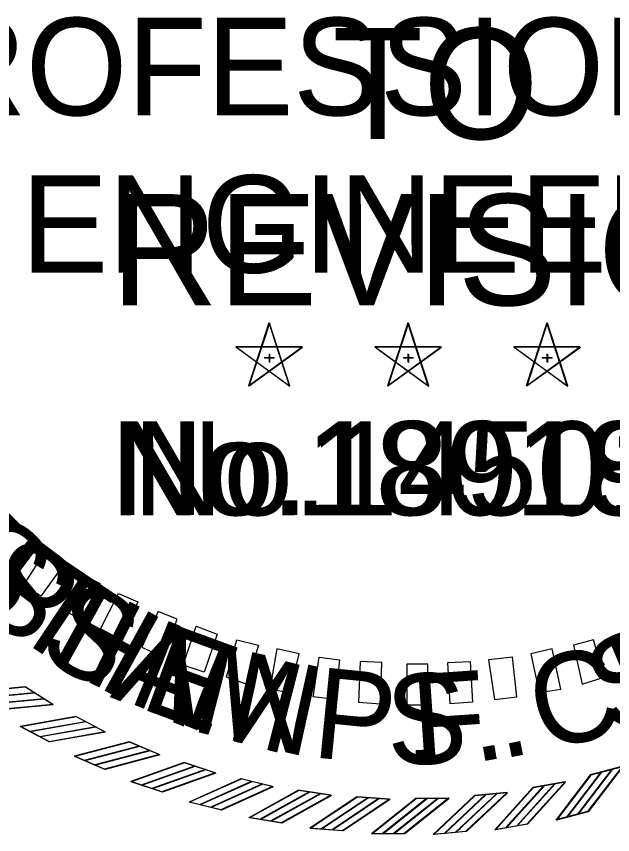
# Model space of a CAD drawing. Extents: x 16 to 1228740, y 11 to 152440.
# Drawn here: x 17.7202 to 17.7889, y 10.8149 to 10.9091 of the extents above; entities that cross this region are included whole.
import ezdxf

# ---------------------------------------------------------------- set-up
doc = ezdxf.new("R2010")
doc.units = 0
for name, color, linetype in [('STAMP_FRED', 7, 'Continuous'), ('STAMP_HUSSAM', 7, 'Continuous'), ('STAMP_JUSTIN', 7, 'Continuous'), ('STAMP_PRELIM', 7, 'Continuous')]:
    doc.layers.add(name, color=color, linetype=linetype)

msp = doc.modelspace()

# ---------------------------------------------------------------- linework, layer by layer
at = {"layer": 'STAMP_FRED'}
for p, q in [((17.749354, 10.873788), (17.746995, 10.866552)), ((17.751704, 10.866556), (17.749359, 10.873797)), ((17.765345, 10.873788), (17.762986, 10.866552)), ((17.767695, 10.866556), (17.76535, 10.873797)), ((17.781336, 10.873788), (17.778977, 10.866552)), ((17.783686, 10.866556), (17.781341, 10.873797)), ((17.753156, 10.871026), (17.745545, 10.871033)), ((17.745552, 10.871026), (17.751705, 10.866547)), ((17.747004, 10.866556), (17.753165, 10.871024)), ((17.769147, 10.871026), (17.761536, 10.871033)), ((17.761543, 10.871026), (17.767696, 10.866547)), ((17.762995, 10.866556), (17.769157, 10.871024)), ((17.785138, 10.871026), (17.777527, 10.871033)), ((17.777534, 10.871026), (17.783687, 10.866547)), ((17.778986, 10.866556), (17.785148, 10.871024)), ((17.748812, 10.86981), (17.749943, 10.86981)), ((17.749361, 10.870216), (17.749361, 10.869262)), ((17.764803, 10.86981), (17.765934, 10.86981)), ((17.765352, 10.870216), (17.765352, 10.869262)), ((17.780794, 10.86981), (17.781926, 10.86981)), ((17.781343, 10.870216), (17.781343, 10.869262)), ((17.724453, 10.82985), (17.721271, 10.831887)), ((17.730467, 10.826715), (17.727127, 10.828483)), ((17.724043, 10.825577), (17.720711, 10.82734)), ((17.736719, 10.824088), (17.733245, 10.825574)), ((17.730412, 10.822423), (17.726946, 10.823905)), ((17.743167, 10.821986), (17.739582, 10.82318)), ((17.789989, 10.822716), (17.786335, 10.821755)), ((17.737019, 10.819806), (17.733442, 10.820997)), ((17.749767, 10.820424), (17.746096, 10.821318)), ((17.783441, 10.820949), (17.77972, 10.820293)), ((17.756473, 10.819412), (17.75274, 10.82)), ((17.77677, 10.819729), (17.773007, 10.819382)), ((17.743819, 10.817743), (17.740156, 10.818635)), ((17.76324, 10.818958), (17.759471, 10.819235)), ((17.770021, 10.819064), (17.766242, 10.819029)), ((17.750767, 10.81625), (17.747043, 10.816836)), ((17.786034, 10.817528), (17.782388, 10.816569)), ((17.779072, 10.816105), (17.775359, 10.81545)), ((17.757815, 10.815335), (17.754055, 10.815611)), ((17.764913, 10.815005), (17.761144, 10.81497)), ((17.772015, 10.815262), (17.768261, 10.814916))]:
    msp.add_line(p, q, dxfattribs=at)
for points in [[(17.721273, 10.831883), (17.714778, 10.831278)], [(17.722324, 10.831196), (17.715829, 10.830591)], [(17.723443, 10.830514), (17.716948, 10.829909)], [(17.724459, 10.82985), (17.717964, 10.829245)], [(17.72713, 10.828479), (17.720707, 10.827339)], [(17.728235, 10.827881), (17.721812, 10.826742)], [(17.729406, 10.827294), (17.722983, 10.826155)], [(17.730473, 10.826716), (17.72405, 10.825577)], [(17.733248, 10.82557), (17.726941, 10.823904)], [(17.734398, 10.825065), (17.728091, 10.8234)], [(17.735614, 10.824577), (17.729307, 10.822911)], [(17.736725, 10.82409), (17.730418, 10.822424)], [(17.739586, 10.823176), (17.733438, 10.820996)], [(17.740774, 10.822769), (17.734626, 10.820588)], [(17.742025, 10.822382), (17.735877, 10.820201)], [(17.788816, 10.822423), (17.784862, 10.817235)], [(17.789992, 10.822721), (17.786038, 10.817533)], [(17.743173, 10.821988), (17.737025, 10.819807)], [(17.78634, 10.821754), (17.782386, 10.816565)], [(17.787557, 10.822062), (17.783603, 10.816874)], [(17.746099, 10.821314), (17.740152, 10.818633)], [(17.747317, 10.821006), (17.74137, 10.818325)], [(17.748596, 10.820724), (17.742649, 10.818043)], [(17.780964, 10.820498), (17.776595, 10.815654)], [(17.782248, 10.820754), (17.777879, 10.81591)], [(17.783445, 10.820954), (17.779076, 10.81611)], [(17.749772, 10.820427), (17.743826, 10.817746)], [(17.752744, 10.819997), (17.747039, 10.816834)], [(17.753983, 10.81979), (17.748278, 10.816627)], [(17.755281, 10.819615), (17.749576, 10.816452)], [(17.775565, 10.819633), (17.770811, 10.815166)], [(17.776774, 10.819733), (17.77202, 10.815266)], [(17.779725, 10.820291), (17.775356, 10.815447)], [(17.756478, 10.819415), (17.750773, 10.816252)], [(17.759475, 10.819232), (17.754051, 10.815609)], [(17.760727, 10.819128), (17.755303, 10.815505)], [(17.762035, 10.819061), (17.756611, 10.815438)], [(17.763245, 10.818961), (17.75782, 10.815338)], [(17.766247, 10.819026), (17.76114, 10.814967)], [(17.767503, 10.819026), (17.762396, 10.814967)], [(17.768812, 10.819067), (17.763705, 10.815008)], [(17.770025, 10.819067), (17.764919, 10.815008)], [(17.773012, 10.81938), (17.768258, 10.814913)], [(17.774264, 10.819484), (17.76951, 10.815017)]]:
    msp.add_lwpolyline(points, dxfattribs=at)
at = {"layer": 'STAMP_HUSSAM'}
for p, q in [((17.749298, 10.873819), (17.746939, 10.866583)), ((17.751648, 10.866587), (17.749303, 10.873827)), ((17.765289, 10.873819), (17.76293, 10.866583)), ((17.767639, 10.866587), (17.765294, 10.873827)), ((17.78128, 10.873819), (17.778922, 10.866583)), ((17.78363, 10.866587), (17.781285, 10.873827)), ((17.7531, 10.871057), (17.745489, 10.871064)), ((17.745496, 10.871057), (17.751649, 10.866577)), ((17.746948, 10.866587), (17.75311, 10.871055)), ((17.769091, 10.871057), (17.761481, 10.871064)), ((17.761487, 10.871057), (17.76764, 10.866577)), ((17.762939, 10.866587), (17.769101, 10.871055)), ((17.785082, 10.871057), (17.777472, 10.871064)), ((17.777478, 10.871057), (17.783631, 10.866577)), ((17.77893, 10.866587), (17.785092, 10.871055)), ((17.748756, 10.869841), (17.749887, 10.869841)), ((17.749305, 10.870247), (17.749305, 10.869292)), ((17.764747, 10.869841), (17.765879, 10.869841)), ((17.765296, 10.870247), (17.765296, 10.869292)), ((17.780738, 10.869841), (17.78187, 10.869841)), ((17.781287, 10.870247), (17.781287, 10.869292)), ((17.724397, 10.829881), (17.721215, 10.831918)), ((17.730411, 10.826746), (17.727072, 10.828514)), ((17.723988, 10.825607), (17.720656, 10.827371)), ((17.736664, 10.824119), (17.733189, 10.825605)), ((17.730356, 10.822454), (17.72689, 10.823936)), ((17.743112, 10.822017), (17.739527, 10.823211)), ((17.789933, 10.822747), (17.786279, 10.821786)), ((17.736963, 10.819837), (17.733386, 10.821028)), ((17.749711, 10.820455), (17.74604, 10.821349)), ((17.783386, 10.82098), (17.779664, 10.820324)), ((17.756417, 10.819443), (17.752685, 10.820031)), ((17.776714, 10.81976), (17.772952, 10.819413)), ((17.743764, 10.817774), (17.740101, 10.818666)), ((17.763184, 10.818989), (17.759415, 10.819266)), ((17.769965, 10.819094), (17.766187, 10.81906)), ((17.750711, 10.81628), (17.746987, 10.816867)), ((17.785978, 10.817559), (17.782332, 10.8166)), ((17.779016, 10.816136), (17.775303, 10.815481)), ((17.757759, 10.815365), (17.753999, 10.815642)), ((17.764858, 10.815035), (17.761088, 10.815001)), ((17.771959, 10.815293), (17.768205, 10.814947))]:
    msp.add_line(p, q, dxfattribs=at)
for points in [[(17.721217, 10.831914), (17.714722, 10.831309)], [(17.722269, 10.831227), (17.715773, 10.830622)], [(17.723387, 10.830545), (17.716892, 10.82994)], [(17.724403, 10.829881), (17.717908, 10.829276)], [(17.727074, 10.82851), (17.720651, 10.82737)], [(17.728179, 10.827912), (17.721756, 10.826773)], [(17.72935, 10.827325), (17.722927, 10.826185)], [(17.730417, 10.826747), (17.723994, 10.825608)], [(17.733192, 10.825601), (17.726885, 10.823935)], [(17.734343, 10.825096), (17.728036, 10.823431)], [(17.735558, 10.824608), (17.729251, 10.822942)], [(17.736669, 10.824121), (17.730362, 10.822455)], [(17.73953, 10.823207), (17.733382, 10.821026)], [(17.740718, 10.822799), (17.73457, 10.820619)], [(17.741969, 10.822413), (17.735822, 10.820232)], [(17.78876, 10.822454), (17.784806, 10.817266)], [(17.789937, 10.822752), (17.785983, 10.817564)], [(17.743117, 10.822019), (17.736969, 10.819838)], [(17.786284, 10.821785), (17.78233, 10.816596)], [(17.787501, 10.822093), (17.783547, 10.816905)], [(17.746043, 10.821345), (17.740097, 10.818664)], [(17.747261, 10.821037), (17.741314, 10.818356)], [(17.74854, 10.820755), (17.742593, 10.818074)], [(17.780908, 10.820529), (17.776539, 10.815685)], [(17.782192, 10.820785), (17.777824, 10.815941)], [(17.783389, 10.820984), (17.77902, 10.81614)], [(17.749717, 10.820457), (17.74377, 10.817776)], [(17.752689, 10.820027), (17.746983, 10.816865)], [(17.753927, 10.819821), (17.748222, 10.816658)], [(17.755225, 10.819646), (17.74952, 10.816483)], [(17.775509, 10.819663), (17.770755, 10.815197)], [(17.776718, 10.819764), (17.771964, 10.815297)], [(17.779669, 10.820322), (17.7753, 10.815478)], [(17.756422, 10.819446), (17.750717, 10.816283)], [(17.75942, 10.819263), (17.753995, 10.81564)], [(17.760671, 10.819159), (17.755247, 10.815536)], [(17.761979, 10.819092), (17.756555, 10.815469)], [(17.763189, 10.818992), (17.757764, 10.815368)], [(17.766191, 10.819057), (17.761084, 10.814998)], [(17.767447, 10.819057), (17.76234, 10.814998)], [(17.768756, 10.819098), (17.76365, 10.815039)], [(17.76997, 10.819098), (17.764863, 10.815039)], [(17.772956, 10.819411), (17.768202, 10.814944)], [(17.774208, 10.819514), (17.769454, 10.815048)]]:
    msp.add_lwpolyline(points, dxfattribs=at)
at = {"layer": 'STAMP_JUSTIN'}
for p, q in [((17.749354, 10.87379), (17.746995, 10.866554)), ((17.751704, 10.866558), (17.749359, 10.873798)), ((17.765345, 10.87379), (17.762986, 10.866554)), ((17.767695, 10.866558), (17.76535, 10.873798)), ((17.781336, 10.87379), (17.778977, 10.866554)), ((17.783685, 10.866558), (17.78134, 10.873798)), ((17.753156, 10.871028), (17.745545, 10.871035)), ((17.745552, 10.871028), (17.751705, 10.866548)), ((17.747004, 10.866558), (17.753165, 10.871025)), ((17.769147, 10.871028), (17.761536, 10.871035)), ((17.761543, 10.871028), (17.767696, 10.866548)), ((17.762995, 10.866558), (17.769156, 10.871025)), ((17.785138, 10.871028), (17.777527, 10.871035)), ((17.777534, 10.871028), (17.783686, 10.866548)), ((17.778986, 10.866558), (17.785147, 10.871025)), ((17.748812, 10.869812), (17.749943, 10.869812)), ((17.749361, 10.870218), (17.749361, 10.869263)), ((17.764803, 10.869812), (17.765934, 10.869812)), ((17.765352, 10.870218), (17.765352, 10.869263)), ((17.780794, 10.869812), (17.781925, 10.869812)), ((17.781343, 10.870218), (17.781343, 10.869263)), ((17.724454, 10.829852), (17.721271, 10.83189)), ((17.730468, 10.826718), (17.727128, 10.828486)), ((17.724044, 10.825579), (17.720712, 10.827343)), ((17.73672, 10.824091), (17.733246, 10.825577)), ((17.730412, 10.822426), (17.726946, 10.823908)), ((17.743168, 10.821989), (17.739583, 10.823183)), ((17.789988, 10.822719), (17.786334, 10.821758)), ((17.737019, 10.819809), (17.733443, 10.821)), ((17.749767, 10.820427), (17.746096, 10.821321)), ((17.783441, 10.820952), (17.77972, 10.820296)), ((17.756473, 10.819415), (17.75274, 10.820003)), ((17.77677, 10.819732), (17.773007, 10.819385)), ((17.74382, 10.817746), (17.740157, 10.818638)), ((17.76324, 10.818961), (17.759471, 10.819238)), ((17.770021, 10.819066), (17.766242, 10.819032)), ((17.750767, 10.816252), (17.747043, 10.816839)), ((17.786033, 10.817531), (17.782388, 10.816572)), ((17.779071, 10.816108), (17.775358, 10.815453)), ((17.757815, 10.815338), (17.754055, 10.815614)), ((17.764913, 10.815008), (17.761143, 10.814973)), ((17.772015, 10.815265), (17.768261, 10.814919))]:
    msp.add_line(p, q, dxfattribs=at)
for points in [[(17.721274, 10.831885), (17.714779, 10.83128)], [(17.722325, 10.831198), (17.71583, 10.830593)], [(17.723444, 10.830517), (17.716949, 10.829912)], [(17.724459, 10.829853), (17.717964, 10.829248)], [(17.727131, 10.828481), (17.720708, 10.827342)], [(17.728235, 10.827884), (17.721812, 10.826744)], [(17.729406, 10.827297), (17.722983, 10.826157)], [(17.730473, 10.826719), (17.724051, 10.82558)], [(17.733249, 10.825573), (17.726942, 10.823907)], [(17.734399, 10.825068), (17.728092, 10.823403)], [(17.735614, 10.82458), (17.729308, 10.822914)], [(17.736726, 10.824092), (17.730419, 10.822427)], [(17.739586, 10.823179), (17.733438, 10.820998)], [(17.740774, 10.822771), (17.734626, 10.820591)], [(17.742026, 10.822385), (17.735878, 10.820204)], [(17.788815, 10.822426), (17.784862, 10.817238)], [(17.789992, 10.822724), (17.786038, 10.817536)], [(17.743173, 10.821991), (17.737026, 10.81981)], [(17.786339, 10.821757), (17.782385, 10.816568)], [(17.787556, 10.822065), (17.783602, 10.816877)], [(17.7461, 10.821317), (17.740153, 10.818636)], [(17.747317, 10.821009), (17.74137, 10.818328)], [(17.748596, 10.820727), (17.74265, 10.818046)], [(17.780963, 10.820501), (17.776594, 10.815657)], [(17.782248, 10.820757), (17.777879, 10.815913)], [(17.783445, 10.820956), (17.779076, 10.816112)], [(17.749772, 10.820429), (17.743826, 10.817748)], [(17.752744, 10.82), (17.747039, 10.816837)], [(17.753983, 10.819793), (17.748278, 10.81663)], [(17.755281, 10.819618), (17.749576, 10.816455)], [(17.775565, 10.819635), (17.770811, 10.815169)], [(17.776774, 10.819736), (17.77202, 10.815269)], [(17.779724, 10.820294), (17.775356, 10.81545)], [(17.756478, 10.819418), (17.750773, 10.816255)], [(17.759475, 10.819235), (17.754051, 10.815612)], [(17.760727, 10.819131), (17.755303, 10.815508)], [(17.762035, 10.819064), (17.756611, 10.815441)], [(17.763244, 10.818964), (17.75782, 10.815341)], [(17.766247, 10.819029), (17.76114, 10.81497)], [(17.767502, 10.819029), (17.762396, 10.81497)], [(17.768812, 10.81907), (17.763705, 10.815011)], [(17.770025, 10.81907), (17.764919, 10.815011)], [(17.773012, 10.819383), (17.768258, 10.814916)], [(17.774263, 10.819486), (17.769509, 10.81502)]]:
    msp.add_lwpolyline(points, dxfattribs=at)
at = {"layer": 'STAMP_PRELIM'}
for p, q in [((17.719777, 10.850475), (17.72171, 10.848908)), ((17.72171, 10.848908), (17.718902, 10.845283)), ((17.721085, 10.843658), (17.723652, 10.847658)), ((17.723652, 10.847658), (17.725835, 10.846225)), ((17.725835, 10.846225), (17.723027, 10.84235)), ((17.72771, 10.84485), (17.725585, 10.840783)), ((17.729902, 10.843783), (17.72771, 10.84485)), ((17.723027, 10.84235), (17.721085, 10.843658)), ((17.727585, 10.839725), (17.729902, 10.843783)), ((17.729902, 10.8386), (17.73196, 10.842658)), ((17.73196, 10.842658), (17.73421, 10.841725)), ((17.73421, 10.841725), (17.732277, 10.83735)), ((17.725585, 10.840783), (17.727585, 10.839725)), ((17.736527, 10.8406), (17.734652, 10.836475)), ((17.73871, 10.839725), (17.736527, 10.8406)), ((17.737085, 10.83535), (17.73871, 10.839725)), ((17.732277, 10.83735), (17.729902, 10.8386)), ((17.739402, 10.834408), (17.740902, 10.838908)), ((17.740902, 10.838908), (17.743335, 10.837975)), ((17.743335, 10.837975), (17.741835, 10.8336)), ((17.744402, 10.833033), (17.745585, 10.83735)), ((17.745585, 10.83735), (17.748085, 10.836725)), ((17.748085, 10.836725), (17.74671, 10.832225)), ((17.786652, 10.83735), (17.784335, 10.836725)), ((17.784335, 10.836725), (17.785335, 10.832225)), ((17.787902, 10.833033), (17.786652, 10.83735)), ((17.734652, 10.836475), (17.737085, 10.83535)), ((17.75021, 10.836283), (17.749402, 10.831658)), ((17.752777, 10.835725), (17.75021, 10.836283)), ((17.75171, 10.831283), (17.752777, 10.835725)), ((17.781902, 10.836283), (17.77946, 10.835725)), ((17.77946, 10.835725), (17.780402, 10.831283)), ((17.782902, 10.831658), (17.781902, 10.836283)), ((17.754402, 10.830783), (17.755085, 10.83535)), ((17.755085, 10.83535), (17.757402, 10.835033)), ((17.757402, 10.835033), (17.75696, 10.830475)), ((17.759777, 10.83485), (17.759585, 10.830158)), ((17.762277, 10.834725), (17.759777, 10.83485)), ((17.762152, 10.829975), (17.762277, 10.834725)), ((17.769902, 10.834725), (17.77246, 10.83485)), ((17.770152, 10.829975), (17.769902, 10.834725)), ((17.77246, 10.83485), (17.77271, 10.830158)), ((17.777335, 10.83535), (17.774585, 10.835033)), ((17.774585, 10.835033), (17.775277, 10.830475)), ((17.777835, 10.830783), (17.777335, 10.83535)), ((17.741835, 10.8336), (17.739402, 10.834408)), ((17.765152, 10.834533), (17.765152, 10.82985)), ((17.767585, 10.834533), (17.765152, 10.834533)), ((17.767585, 10.82985), (17.767585, 10.834533)), ((17.74671, 10.832225), (17.744402, 10.833033)), ((17.785335, 10.832225), (17.787902, 10.833033)), ((17.749402, 10.831658), (17.75171, 10.831283)), ((17.780402, 10.831283), (17.782902, 10.831658)), ((17.75696, 10.830475), (17.754402, 10.830783)), ((17.759585, 10.830158), (17.762152, 10.829975)), ((17.77271, 10.830158), (17.770152, 10.829975)), ((17.775277, 10.830475), (17.777835, 10.830783)), ((17.765152, 10.82985), (17.767585, 10.82985))]:
    msp.add_line(p, q, dxfattribs=at)

# ---------------------------------------------------------------- texts
at = {"layer": 'STAMP_FRED'}
for s, height, p in [('PROFESSIONAL', 0.01119382, (17.700561, 10.897711)), ('ENGINEER', 0.0111938, (17.720817, 10.879588)), ('No.14501', 0.010794, (17.733619, 10.851677))]:
    msp.add_text(s, height=height, dxfattribs=at).set_placement(p)
for s, rotation, p in [('E', 315.39049, (17.707475, 10.848997)), ('P', 323.0513, (17.714924, 10.841696)), ('H', 331.07691, (17.723698, 10.835185)), ('H', 22.87857, (17.791437, 10.827269)), ('E', 339.83212, (17.734202, 10.829556)), ('N', 347.49293, (17.744004, 10.825992)), ('F', 3.90895, (17.76608, 10.822912)), ('.', 11.20496, (17.775991, 10.82359))]:
    msp.add_text(s, height=0.010417, rotation=rotation, dxfattribs=at).set_placement(p)
at = {"layer": 'STAMP_HUSSAM'}
for s, height, p in [('PROFESSIONAL', 0.01119382, (17.700506, 10.897742)), ('ENGINEER', 0.0111938, (17.720761, 10.879619)), ('No.18919', 0.010794, (17.731422, 10.851708))]:
    msp.add_text(s, height=height, dxfattribs=at).set_placement(p)
for s, rotation, p in [('S', 323.71697, (17.714331, 10.841684)), ('S', 331.00477, (17.722272, 10.835699)), ('A', 338.29258, (17.730907, 10.830771)), ('S', 21.65504, (17.788534, 10.826346)), ('M', 345.58039, (17.740098, 10.826978)), ('S', 2.70674, (17.763022, 10.822844)), ('.', 9.99454, (17.772959, 10.823189))]:
    msp.add_text(s, height=0.010417, rotation=rotation, dxfattribs=at).set_placement(p)
at = {"layer": 'STAMP_JUSTIN'}
for s, height, p in [('PROFESSIONAL', 0.01119355, (17.700563, 10.897712)), ('ENGINEER', 0.0111936, (17.720818, 10.879589)), ('No.18018', 0.0107938, (17.731051, 10.851679))]:
    msp.add_text(s, height=height, dxfattribs=at).set_placement(p)
for s, rotation, p in [('S', 318.95995, (17.711573, 10.844822)), ('T', 326.25596, (17.719143, 10.838401)), ('I', 333.55197, (17.727467, 10.832993)), ('N', 337.92957, (17.732768, 10.830271)), ('C', 14.04482, (17.780774, 10.824438)), ('P', 354.34559, (17.754093, 10.823842)), ('.', 2.3712, (17.764976, 10.822974))]:
    msp.add_text(s, height=0.010416, rotation=rotation, dxfattribs=at).set_placement(p)
at = {"layer": 'STAMP_PRELIM'}
for s, p in [('TO', (17.756585, 10.894975)), ('REVISION', (17.731085, 10.87585))]:
    msp.add_text(s, height=0.0127938, dxfattribs=at).set_placement(p)

doc.saveas('drawing.dxf')
